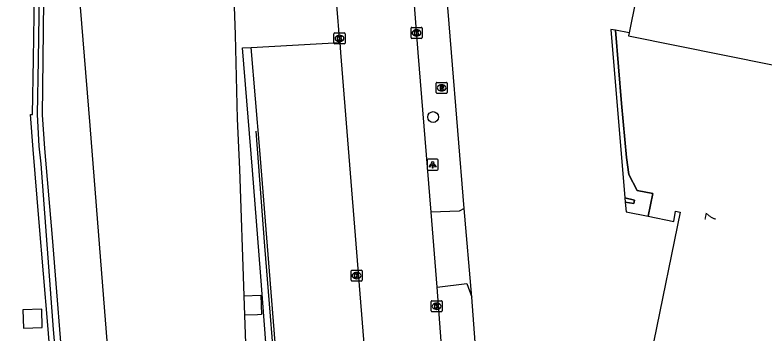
# Model space of a CAD drawing. Extents: x 157692 to 159670, y 381454 to 383289.
# Drawn here: x 157852.5 to 157920.5, y 381866.4 to 381895.3 of the extents above; entities that cross this region are included whole.
import ezdxf

# ---------------------------------------------------------------- set-up
doc = ezdxf.new("R2010")
doc.units = 0
for name, color, linetype in [('IMGEO_Berm_gesloten', 7, 'Continuous'), ('IMGEO_Berm_groen', 7, 'Continuous'), ('IMGEO_Boom', 7, 'Continuous'), ('IMGEO_Brandkraan', 7, 'Continuous'), ('IMGEO_Geluidsscherm', 7, 'Continuous'), ('IMGEO_Kolk', 7, 'Continuous'), ('IMGEO_Lichtpunt', 7, 'Continuous'), ('IMGEO_Muur', 7, 'Continuous'), ('IMGEO_Pand', 7, 'Continuous'), ('IMGEO_Pand_nummerreeks', 7, 'Continuous'), ('IMGEO_Pand_overbouw', 7, 'Continuous'), ('IMGEO_Rijbaan_autoweg', 7, 'Continuous'), ('IMGEO_Rijbaan_lokaal_open', 7, 'Continuous'), ('IMGEO_Voetpad_open', 7, 'Continuous')]:
    doc.layers.add(name, color=color, linetype=linetype)

msp = doc.modelspace()

# ---------------------------------------------------------------- linework, layer by layer
at = {"layer": 'IMGEO_Berm_gesloten'}
msp.add_lwpolyline([(157873.308, 381869.813), (157874.859, 381869.874), (157874.928, 381868.11), (157874.554, 381868.095), (157873.377, 381868.049)], dxfattribs=at)
at = {"layer": 'IMGEO_Berm_groen'}
for points in [[(157873.989, 381892.369), (157882.034, 381892.833)], [(157853.255, 381868.561), (157853.299, 381866.884), (157855.022, 381866.929), (157854.978, 381868.606), (157853.255, 381868.561)]]:
    msp.add_lwpolyline(points, dxfattribs=at)
at = {"layer": 'IMGEO_Boom'}
msp.add_circle((157890.506, 381886.059), 0.489, dxfattribs=at)
at = {"layer": 'IMGEO_Brandkraan'}
for p, q in [((157890.783, 381888.281), (157890.783, 381889.133)), ((157890.858, 381889.207), (157891.71, 381889.207)), ((157891.271, 381888.987), (157891.296, 381888.987)), ((157891.784, 381889.133), (157891.784, 381888.281)), ((157891.71, 381888.207), (157890.858, 381888.207)), ((157891.294, 381888.427), (157891.269, 381888.427))]:
    msp.add_line(p, q, dxfattribs=at)
for points in [[(157890.783, 381888.281), (157890.783, 381889.133)], [(157890.858, 381889.207), (157891.71, 381889.207)], [(157891.131, 381888.907), (157891.131, 381888.507), (157891.344, 381888.507)], [(157891.362, 381888.907), (157891.131, 381888.907)], [(157891.31, 381888.826), (157891.256, 381888.826), (157891.256, 381888.75)], [(157891.784, 381889.133), (157891.784, 381888.281)], [(157891.71, 381888.207), (157890.858, 381888.207)], [(157891.256, 381888.75), (157891.309, 381888.75)], [(157891.318, 381888.674), (157891.256, 381888.674), (157891.256, 381888.593)], [(157891.256, 381888.593), (157891.318, 381888.593)]]:
    msp.add_lwpolyline(points, dxfattribs=at)
for centre, radius, start, end in [((157890.86, 381889.131), 0.0765, 91.55205, 178.44795), ((157890.86, 381889.131), 0.0765, 91.55205, 178.44795), ((157891.311, 381888.788), 0.0379, 267.82845, 90.93552), ((157891.366, 381888.762), 0.145, 59.4692, 91.53667), ((157891.391, 381888.809), 0.0922, 285.51372, 58.15012), ((157891.708, 381889.131), 0.0765, 1.55205, 88.44795), ((157891.708, 381889.131), 0.0765, 1.55205, 88.44795), ((157890.86, 381888.283), 0.0765, 181.55205, 268.44795), ((157890.86, 381888.283), 0.0765, 181.55205, 268.44795), ((157891.319, 381888.633), 0.0404, 269.87594, 90.50774), ((157891.35, 381888.758), 0.251, 268.66757, 293.53466), ((157891.396, 381888.617), 0.105, 301.31148, 78.98903), ((157891.708, 381888.283), 0.0765, 271.55205, 358.44795), ((157891.708, 381888.283), 0.0765, 271.55205, 358.44795)]:
    msp.add_arc(centre, radius, start, end, dxfattribs=at)
for centre, major_axis, ratio, start_param, end_param in [((157891.27, 381888.707), (-0.387, 0.002), 0.722429, 4.712389, 7.853982), ((157891.295, 381888.707), (-0.39, 0.002), 0.717154, 1.570796, 4.712389)]:
    msp.add_ellipse(centre, major_axis=major_axis, ratio=ratio, start_param=start_param, end_param=end_param, dxfattribs=at)
at = {"layer": 'IMGEO_Geluidsscherm'}
for points in [[(157854.585, 381886.29), (157854.67, 381891.251), (157854.804, 381899.361), (157854.886, 381906.821), (157854.636, 381909.954), (157854.03, 381918.198)], [(157874.053, 381638.712), (157872.666, 381656.094), (157871.737, 381668.027), (157870.721, 381681.637), (157869.567, 381696.23), (157868.32, 381712.586), (157867.159, 381726.489), (157865.954, 381741.209), (157864.809, 381756.45), (157863.806, 381768.982), (157862.385, 381786.19), (157861.408, 381800.707), (157860.147, 381816.502), (157858.882, 381832.382), (157857.547, 381849.595), (157856.042, 381866.756), (157854.906, 381881.824), (157854.737, 381883.41), (157854.585, 381886.29)], [(157894.139, 381641.124), (157893.247, 381651.551), (157892.35, 381662.063), (157891.41, 381672.573), (157890.762, 381680.814), (157889.905, 381691.372), (157889.058, 381701.758), (157888.118, 381712.268), (157887.113, 381724.843), (157885.957, 381739.479), (157885.015, 381750.851), (157883.817, 381765.443), (157882.659, 381780.122), (157881.699, 381792.657), (157880.689, 381805.318), (157879.686, 381817.851), (157878.57, 381832.532), (157877.418, 381847.083), (157876.408, 381859.744), (157875.211, 381874.335), (157874.447, 381884.768)]]:
    msp.add_lwpolyline(points, dxfattribs=at)
at = {"layer": 'IMGEO_Kolk'}
for p, q in [((157888.576, 381894.2), (157889.428, 381894.2)), ((157881.505, 381892.777), (157881.505, 381893.629)), ((157881.58, 381893.703), (157882.432, 381893.703)), ((157882.506, 381893.629), (157882.506, 381892.777)), ((157888.501, 381893.274), (157888.501, 381894.126)), ((157888.989, 381893.98), (157889.014, 381893.98)), ((157889.502, 381894.126), (157889.502, 381893.274)), ((157882.016, 381892.923), (157881.991, 381892.923)), ((157881.993, 381893.483), (157882.018, 381893.483)), ((157889.428, 381893.2), (157888.576, 381893.2)), ((157889.012, 381893.42), (157888.987, 381893.42)), ((157882.432, 381892.703), (157881.58, 381892.703)), ((157883.057, 381871.23), (157883.057, 381872.082)), ((157883.132, 381872.156), (157883.984, 381872.156)), ((157883.545, 381871.936), (157883.57, 381871.936)), ((157884.058, 381872.082), (157884.058, 381871.23)), ((157883.984, 381871.156), (157883.132, 381871.156)), ((157883.568, 381871.376), (157883.543, 381871.376)), ((157890.326, 381868.447), (157890.326, 381869.299)), ((157890.401, 381869.373), (157891.253, 381869.373)), ((157890.814, 381869.153), (157890.839, 381869.153)), ((157891.327, 381869.299), (157891.327, 381868.447)), ((157891.253, 381868.373), (157890.401, 381868.373)), ((157890.837, 381868.593), (157890.812, 381868.593))]:
    msp.add_line(p, q, dxfattribs=at)
for points in [[(157888.576, 381894.2), (157889.428, 381894.2)], [(157881.505, 381892.777), (157881.505, 381893.629)], [(157881.58, 381893.703), (157882.432, 381893.703)], [(157882.506, 381893.629), (157882.506, 381892.777)], [(157888.501, 381893.274), (157888.501, 381894.126)], [(157888.822, 381893.9), (157888.945, 381893.9), (157888.945, 381893.749), (157889.075, 381893.9), (157889.239, 381893.9), (157889.093, 381893.749), (157889.246, 381893.5), (157889.094, 381893.5), (157889.009, 381893.664), (157888.945, 381893.597), (157888.945, 381893.5), (157888.822, 381893.5), (157888.822, 381893.9)], [(157889.502, 381894.126), (157889.502, 381893.274)], [(157881.826, 381893.403), (157881.949, 381893.403), (157881.949, 381893.252), (157882.079, 381893.403), (157882.243, 381893.403), (157882.097, 381893.252), (157882.25, 381893.003), (157882.098, 381893.003), (157882.013, 381893.167), (157881.949, 381893.1), (157881.949, 381893.003), (157881.826, 381893.003), (157881.826, 381893.403)], [(157889.428, 381893.2), (157888.576, 381893.2)], [(157882.432, 381892.703), (157881.58, 381892.703)], [(157883.057, 381871.23), (157883.057, 381872.082)], [(157883.132, 381872.156), (157883.984, 381872.156)], [(157883.378, 381871.856), (157883.501, 381871.856), (157883.501, 381871.705), (157883.631, 381871.856), (157883.795, 381871.856), (157883.649, 381871.705), (157883.802, 381871.456), (157883.65, 381871.456), (157883.565, 381871.62), (157883.501, 381871.553), (157883.501, 381871.456), (157883.378, 381871.456), (157883.378, 381871.856)], [(157884.058, 381872.082), (157884.058, 381871.23)], [(157883.984, 381871.156), (157883.132, 381871.156)], [(157890.326, 381868.447), (157890.326, 381869.299)], [(157890.401, 381869.373), (157891.253, 381869.373)], [(157890.647, 381869.073), (157890.77, 381869.073), (157890.77, 381868.922), (157890.9, 381869.073), (157891.064, 381869.073), (157890.918, 381868.922), (157891.071, 381868.673), (157890.919, 381868.673), (157890.834, 381868.837), (157890.77, 381868.77), (157890.77, 381868.673), (157890.647, 381868.673), (157890.647, 381869.073)], [(157891.327, 381869.299), (157891.327, 381868.447)], [(157891.253, 381868.373), (157890.401, 381868.373)]]:
    msp.add_lwpolyline(points, dxfattribs=at)
for centre, start, end in [((157888.578, 381894.124), 91.55205, 178.44795), ((157888.578, 381894.124), 91.55205, 178.44795), ((157889.426, 381894.124), 1.55205, 88.44795), ((157889.426, 381894.124), 1.55205, 88.44795), ((157881.582, 381893.627), 91.55205, 178.44795), ((157881.582, 381893.627), 91.55205, 178.44795), ((157882.43, 381893.627), 1.55205, 88.44795), ((157882.43, 381893.627), 1.55205, 88.44795), ((157888.578, 381893.276), 181.55205, 268.44795), ((157888.578, 381893.276), 181.55205, 268.44795), ((157889.426, 381893.276), 271.55205, 358.44795), ((157889.426, 381893.276), 271.55205, 358.44795), ((157881.582, 381892.779), 181.55205, 268.44795), ((157881.582, 381892.779), 181.55205, 268.44795), ((157882.43, 381892.779), 271.55205, 358.44795), ((157882.43, 381892.779), 271.55205, 358.44795), ((157883.134, 381872.08), 91.55205, 178.44795), ((157883.134, 381872.08), 91.55205, 178.44795), ((157883.982, 381872.08), 1.55205, 88.44795), ((157883.982, 381872.08), 1.55205, 88.44795), ((157883.134, 381871.232), 181.55205, 268.44795), ((157883.134, 381871.232), 181.55205, 268.44795), ((157883.982, 381871.232), 271.55205, 358.44795), ((157883.982, 381871.232), 271.55205, 358.44795), ((157890.403, 381869.297), 91.55205, 178.44795), ((157890.403, 381869.297), 91.55205, 178.44795), ((157891.251, 381869.297), 1.55205, 88.44795), ((157891.251, 381869.297), 1.55205, 88.44795), ((157890.403, 381868.449), 181.55205, 268.44795), ((157890.403, 381868.449), 181.55205, 268.44795), ((157891.251, 381868.449), 271.55205, 358.44795), ((157891.251, 381868.449), 271.55205, 358.44795)]:
    msp.add_arc(centre, 0.0765, start, end, dxfattribs=at)
for centre, major_axis, ratio, start_param, end_param in [((157888.988, 381893.7), (-0.387, 0.002), 0.722429, 4.712389, 7.853982), ((157889.013, 381893.7), (-0.39, 0.002), 0.717154, 1.570796, 4.712389), ((157881.992, 381893.203), (-0.387, 0.002), 0.722429, 4.712389, 7.853982), ((157882.017, 381893.203), (-0.39, 0.002), 0.717154, 1.570796, 4.712389), ((157883.544, 381871.656), (-0.387, 0.002), 0.722429, 4.712389, 7.853982), ((157883.569, 381871.656), (-0.39, 0.002), 0.717154, 1.570796, 4.712389), ((157890.813, 381868.873), (-0.387, 0.002), 0.722429, 4.712389, 7.853982), ((157890.838, 381868.873), (-0.39, 0.002), 0.717154, 1.570796, 4.712389)]:
    msp.add_ellipse(centre, major_axis=major_axis, ratio=ratio, start_param=start_param, end_param=end_param, dxfattribs=at)
at = {"layer": 'IMGEO_Lichtpunt'}
for p, q in [((157889.96, 381882.136), (157889.96, 381881.329)), ((157889.96, 381882.136), (157889.96, 381881.329)), ((157890.862, 381882.231), (157890.054, 381882.231)), ((157890.862, 381882.231), (157890.054, 381882.231)), ((157890.956, 381881.329), (157890.956, 381882.136)), ((157890.956, 381881.329), (157890.956, 381882.136)), ((157890.054, 381881.235), (157890.862, 381881.235)), ((157890.054, 381881.235), (157890.862, 381881.235))]:
    msp.add_line(p, q, dxfattribs=at)
for points in [[(157890.334, 381881.8), (157890.373, 381881.772), (157890.185, 381881.51), (157890.147, 381881.537), (157890.334, 381881.8)], [(157890.436, 381881.752), (157890.483, 381881.752), (157890.483, 381881.43), (157890.436, 381881.43), (157890.436, 381881.752)], [(157890.546, 381881.772), (157890.584, 381881.799), (157890.771, 381881.537), (157890.732, 381881.509), (157890.546, 381881.772)]]:
    msp.add_lwpolyline(points, dxfattribs=at)
msp.add_circle((157890.459, 381881.934), 0.0994, dxfattribs=at)
for centre, start, end in [((157890.054, 381882.136), 90, 180), ((157890.054, 381882.136), 90, 180), ((157890.862, 381882.136), 0, 90), ((157890.862, 381882.136), 0, 90), ((157890.054, 381881.329), 180, 270), ((157890.054, 381881.329), 180, 270), ((157890.862, 381881.329), 270, 0), ((157890.862, 381881.329), 270, 360)]:
    msp.add_arc(centre, 0.0946, start, end, dxfattribs=at)
at = {"layer": 'IMGEO_Muur'}
for points in [[(157858.987, 381823.914), (157858.251, 381833.422), (157857.489, 381842.584), (157856.912, 381850.29), (157856.287, 381857.692), (157855.531, 381867.156), (157854.74, 381876.467), (157854.177, 381883.096), (157853.944, 381886.295), (157854.138, 381886.284), (157854.218, 381891.33), (157854.336, 381899.353), (157854.419, 381906.792), (157854.189, 381909.948), (157853.59, 381918.062), (157853.012, 381926.018), (157852.401, 381934.05), (157851.708, 381942.077)], [(157852.566, 381942.102), (157853.196, 381934.112), (157853.848, 381926.083), (157854.451, 381918.086), (157855.298, 381906.882), (157855.156, 381899.332), (157855.061, 381891.288), (157855.001, 381886.264), (157855.226, 381883.216), (157855.91, 381875.127), (157857.036, 381861.071), (157857.969, 381849.462), (157858.911, 381838.09), (157859.838, 381826.588), (157860.71, 381815.729), (157861.68, 381803.41), (157862.684, 381789.628), (157863.821, 381774.538), (157864.981, 381759.018), (157865.914, 381747.818), (157866.94, 381735.675), (157867.965, 381722.303), (157868.994, 381709.276)], [(157887.932, 381707.729), (157887.155, 381717.191), (157886.515, 381724.851), (157885.711, 381734.42), (157884.966, 381743.588), (157884.182, 381753.692), (157883.34, 381763.97), (157882.447, 381774.827), (157882.173, 381778.304), (157881.488, 381787.341), (157880.879, 381794.83), (157880.152, 381804.166), (157879.468, 381813.482), (157878.811, 381821.896), (157877.88, 381833.462), (157877.286, 381840.672), (157876.321, 381852.904), (157875.521, 381862.797), (157874.824, 381871.962), (157874.1, 381881.234), (157873.193, 381892.349), (157873.989, 381892.369)], [(157889.505, 381698.696), (157888.108, 381715.453), (157887.411, 381723.799), (157886.734, 381732.168), (157886.078, 381740.56), (157885.416, 381748.649), (157884.565, 381759.53), (157883.305, 381774.894), (157881.864, 381793.308), (157881.01, 381804.232), (157880.198, 381814.361), (157879.607, 381821.916), (157878.695, 381833.548), (157877.743, 381845.523), (157876.888, 381856.468), (157876.377, 381862.907), (157875.637, 381872.07), (157874.781, 381883.037), (157873.989, 381892.369)]]:
    msp.add_lwpolyline(points, dxfattribs=at)
at = {"layer": 'IMGEO_Pand'}
for points in [[(157938.747, 381887.286), (157944.3, 381914.71), (157904.685, 381922.789), (157905.313, 381915.326), (157905.785, 381910.423), (157906.033, 381908.878), (157906.776, 381907.399), (157908.122, 381907.136), (157907.725, 381905.084), (157910.03, 381904.625), (157910.224, 381905.502), (157910.655, 381905.415), (157908.294, 381893.7)], [(157908.294, 381893.7), (157907.074, 381893.947), (157907.613, 381887.292), (157908.049, 381882.391), (157908.266, 381880.843), (157909.046, 381879.384), (157910.448, 381879.107), (157910.043, 381877.053), (157912.354, 381876.58), (157912.516, 381877.516), (157912.946, 381877.427), (157910.538, 381865.722)], [(157908.294, 381893.7), (157908.243, 381893.445), (157938.747, 381887.286)], [(157907.943, 381878.335), (157908.726, 381878.196), (157908.78, 381878.522), (157907.903, 381878.715), (157907.943, 381878.335)]]:
    msp.add_lwpolyline(points, dxfattribs=at)
at = {"layer": 'IMGEO_Pand_overbouw'}
msp.add_lwpolyline([(157907.943, 381878.335), (157908.047, 381877.46), (157910.043, 381877.053), (157910.448, 381879.107), (157909.046, 381879.384), (157908.266, 381880.843), (157908.049, 381882.391), (157907.613, 381887.292), (157907.074, 381893.947), (157906.65, 381894.001), (157907.903, 381878.715), (157908.78, 381878.522), (157908.726, 381878.196)], close=True, dxfattribs=at)
at = {"layer": 'IMGEO_Rijbaan_autoweg'}
for points in [[(157868.509, 381953.819), (157870.056, 381934.314), (157871.233, 381917.706), (157872.283, 381900.404), (157872.522, 381893.537), (157872.711, 381885.895), (157872.921, 381881.313), (157873.308, 381869.813)], [(157854.775, 381943.17), (157855.675, 381931.633), (157856.539, 381921.158), (157857.093, 381913.494), (157858.078, 381900.896), (157859.349, 381885.296), (157860.482, 381870.701), (157861.613, 381856.559), (157862.57, 381845.317), (157863.541, 381831.749), (157864.246, 381822.842), (157865.141, 381810.714), (157866.157, 381798.354), (157867.132, 381785.518), (157868.028, 381774.618), (157869.025, 381762.603), (157870.022, 381750.608), (157871.057, 381737.862), (157871.967, 381726.294), (157873, 381713.591), (157873.682, 381705.524)], [(157873.308, 381869.813), (157873.377, 381868.049)], [(157873.377, 381868.049), (157873.585, 381862.1), (157873.92, 381850.557), (157874.303, 381839.407), (157874.844, 381831.878), (157875.738, 381819.514), (157876.969, 381804.757), (157877.974, 381792.105), (157879.326, 381775.432), (157881.117, 381753.472), (157882.892, 381729.72), (157883.254, 381725.724)]]:
    msp.add_lwpolyline(points, dxfattribs=at)
at = {"layer": 'IMGEO_Rijbaan_lokaal_open'}
for points in [[(157882.034, 381892.833), (157881.852, 381895.137), (157881.827, 381895.451), (157881.036, 381905.442), (157880.23, 381915.596), (157879.41, 381924.908)], [(157890.332, 381877.421), (157889.136, 381891.93), (157888.663, 381898.174)], [(157882.034, 381892.833), (157882.108, 381891.93), (157885.063, 381854.884)], [(157890.863, 381870.606), (157890.332, 381877.421)], [(157892.003, 381855.489), (157890.863, 381870.606)]]:
    msp.add_lwpolyline(points, dxfattribs=at)
at = {"layer": 'IMGEO_Voetpad_open'}
for points in [[(157893.325, 381877.753), (157892.172, 381891.93), (157891.624, 381898.653)], [(157893.325, 381877.753), (157892.885, 381877.514), (157890.332, 381877.421)], [(157894.029, 381869.687), (157893.325, 381877.753)], [(157890.863, 381870.606), (157893.574, 381870.934), (157894.029, 381869.687)], [(157895.511, 381849.68), (157894.029, 381869.687)]]:
    msp.add_lwpolyline(points, dxfattribs=at)

# ---------------------------------------------------------------- texts
at = {"layer": 'IMGEO_Pand_nummerreeks'}
msp.add_text('7', height=1, rotation=78.37507, dxfattribs=at).set_placement((157916.104, 381876.497))

doc.saveas('drawing.dxf')
